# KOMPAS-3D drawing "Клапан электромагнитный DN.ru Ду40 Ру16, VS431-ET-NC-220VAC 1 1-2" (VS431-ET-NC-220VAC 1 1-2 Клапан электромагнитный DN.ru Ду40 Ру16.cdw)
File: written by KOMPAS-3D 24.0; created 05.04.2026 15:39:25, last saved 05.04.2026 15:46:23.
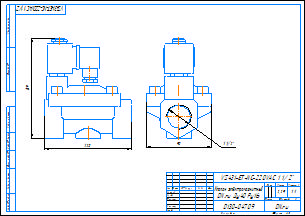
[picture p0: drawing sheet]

Document properties: c3d_UniqueCompID: ef56311e-7521-43dc-8291-0e6108b3d81d; Автор: artio; Класс точности: c; Знак неуказанной шероховатости: Шероховатость не задана; Рассекать на разрезах: Да; c3d_UniqueCompID: ef56311e-7521-43dc-8291-0e6108b3d81d; Автор: artio; Класс точности: c; Знак неуказанной шероховатости: Шероховатость не задана; Рассекать на разрезах: Да; c3d_UniqueCompID: ef56311e-7521-43dc-8291-0e6108b3d81d; Автор: artio; Класс точности: c; Знак неуказанной шероховатости: Шероховатость не задана; Рассекать на разрезах: Да; c3d_UniqueCompID: ef56311e-7521-43dc-8291-0e6108b3d81d; Автор: artio; Класс точности: c; Знак неуказанной шероховатости: Шероховатость не задана; Рассекать на разрезах: Да; Автор: artio; Форматы листов документа: A3; Полное имя файла: VS431-ET-NC-220VAC 1 1-2 Клапан электромагнитный DN.ru Ду40 Ру16.m3d; Масса: 2.285; Наименование: Клапан электромагнитный DN.ru Ду40 Ру16; Количество листов документа: 1; Примечание: D130-04709

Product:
- Body: Тело 1  | qty 1
    Масса: 3.859459
- Part/product: Клапан электромагнитный DN.ru Ду40 Ру16  | designation VS431-ET-NC-220VAC 1 1-2
    Масса: 2.285
    Раздел спецификации: Прочие изделия
    Примечание: D130-04709
    additional columns: ef56311e-7521-43dc-8291-0e6108b3d81d; artio; c; Шероховатость не задана; Да

Views: Вид 1, Спереди
Referenced files in C:\Users\artio\OneDrive\Рабочий стол\Клапан электромагнитный DN.ru\VS431\VS431-ET-NC\: VS431-ET-NC-220VAC 3-4 Клапан электромагнитный DN.ru Ду20 Ру16.m3d, VS431-ET-NC-220VAC 1 1-2 Клапан электромагнитный DN.ru Ду40 Ру16.m3d, VS431-ET-NC-220VAC 3-4 Клапан электромагнитный DN.ru Ду20 Ру16.cdw
Referenced files in C:\Users\artio\OneDrive\Рабочий стол\Клапан электромагнитный DN.ru\VS431\VS431-ET-NC\VS431-ET-NC-220VAC\Ду40\: VS431-ET-NC-220VAC 1 1-2 Клапан электромагнитный DN.ru Ду40 Ру16.m3d
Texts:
  VS431-ET-NC-220VAC 1 1-2
  Клапан электромагнитный
  DN.ru Ду40 Ру16
  VS431-ET-NC-220VAC 1 1/2"
  VS431-ET-NC-220VAC 1 1/2"-
  Клапан электромагнитный DN.ru Ду40 Ру16
  VS431-ET-NC-220VAC 1 1-2 Клапан электромагнитный DN.ru Ду40 Ру16
Dimensions and other numbers on the sheet: 0; 3; 2; 4; 90; 1 1/2"; 1:1; 1; 2,29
